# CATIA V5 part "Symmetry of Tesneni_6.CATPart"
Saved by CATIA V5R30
Part number: Symmetry of Tesneni_6
Bounding box of the stored display mesh (mm): x 0 to 1.2, y -6 to 6, z -6 to 6
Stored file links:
  E:\Bakalarka\Model\Forma_v7\Symmetry of Tesneni_6.CATPart
  E:\Bakalarka\Model\Forma_v7\Tesneni.CATPart
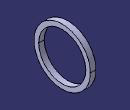
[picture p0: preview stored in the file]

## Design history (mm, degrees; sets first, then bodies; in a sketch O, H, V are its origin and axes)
Body1 (main body)
  Body2 "Body from original PartBody"
    Solid1: linked copy from another document
  Assemble1: tool Body2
